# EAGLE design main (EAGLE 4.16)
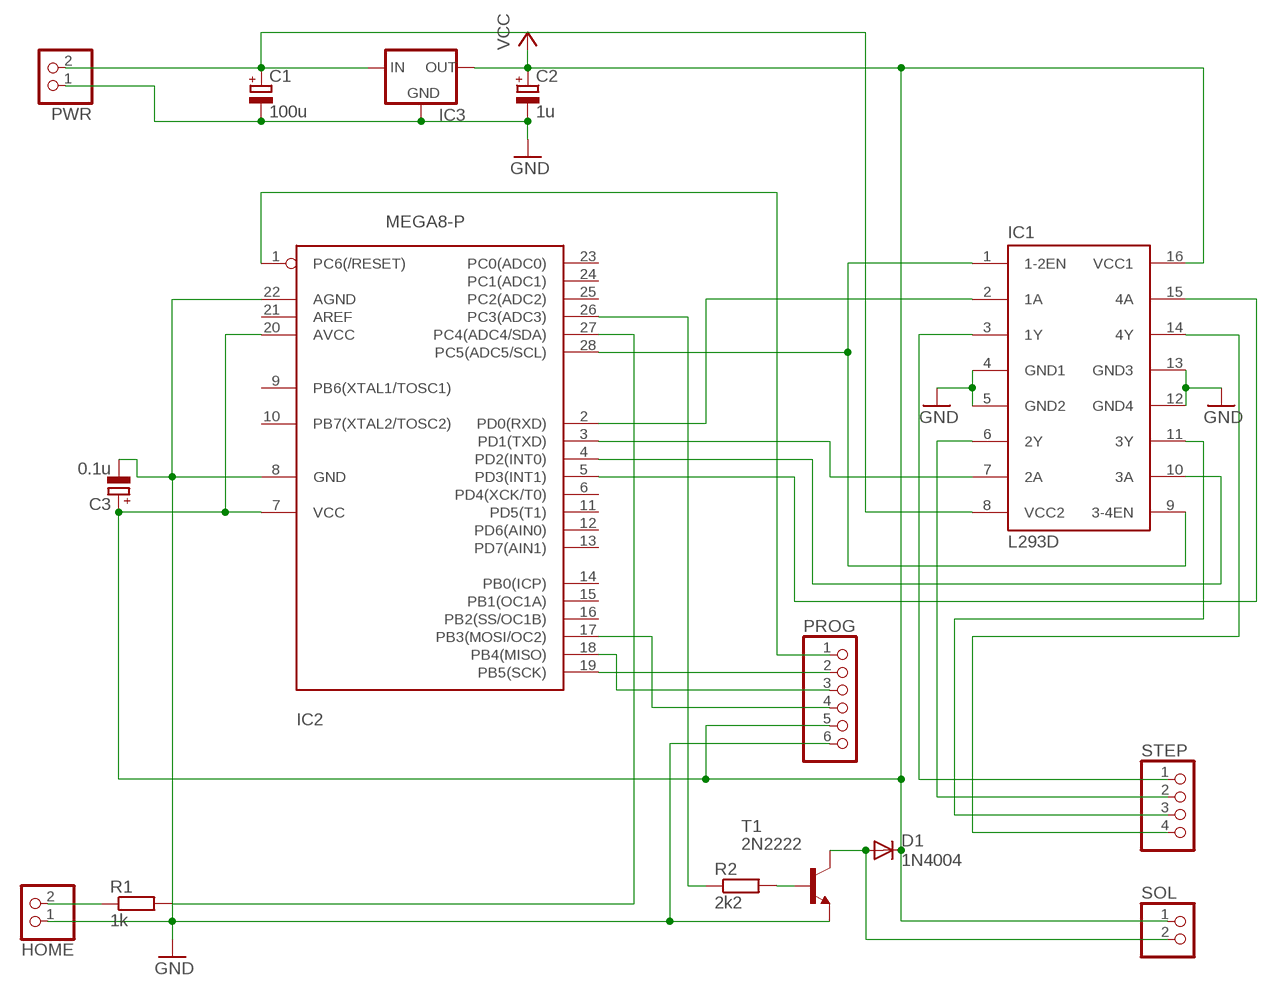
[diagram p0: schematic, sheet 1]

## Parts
C1  100u  CPOL-EUE2.5-7  [E2,5-7]
C2  1u  CPOL-EUE2.5-7  [E2,5-7]
C3  0.1u  CPOL-EUE2.5-7  [E2,5-7]
D1  1N4004  [DO41-10]
HOME  PINHD-1X2  [1X02]
IC1  L293D  [DIL16]
IC2  MEGA8-P  [DIL28-3]
IC3  78XXS  [78XXS]
PROG  PINHD-1X6  [1X06]
PWR  PINHD-1X2  [1X02]
R1  1k  R-EU_0207/2V  [0207/2V]
R2  2k2  R-EU_0207/2V  [0207/2V]
SOL  PINHD-1X2  [1X02]
STEP  PINHD-1X4  [1X04]
T1  2N2222  [TO18]

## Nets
GND: C1.- C2.- C3.- HOME.1 IC1.4(GND1) IC1.5(GND2) IC1.12(GND4) IC1.13(GND3) IC2.8(GND) IC2.22(AGND) IC3.GND PROG.6 PWR.1 T1.1(E)
N$1: C1.+ IC1.8(VCC2) IC3.IN PWR.2
N$2: IC1.3(1Y) STEP.1
N$3: IC1.6(2Y) STEP.2
N$4: IC1.1(1-2EN) IC1.9(3-4EN) IC2.28(PC5(ADC5/SCL))
N$5: IC1.2(1A) IC2.2(PD0(RXD))
N$6: IC1.7(2A) IC2.3(PD1(TXD))
N$7: IC1.10(3A) IC2.4(PD2(INT0))
N$8: IC1.15(4A) IC2.5(PD3(INT1))
N$9: IC1.11(3Y) STEP.3
N$10: IC1.14(4Y) STEP.4
N$11: HOME.2 R1.1
N$12: IC2.27(PC4(ADC4/SDA)) R1.2
N$13: IC2.26(PC3(ADC3)) R2.1
N$14: R2.2 T1.2(B)
N$15: D1.A SOL.2 T1.3(C)
N$16: IC2.1(PC6(/RESET)) PROG.1
N$17: IC2.19(PB5(SCK)) PROG.2
N$18: IC2.18(PB4(MISO)) PROG.3
N$19: IC2.17(PB3(MOSI/OC2)) PROG.4
VCC: C2.+ C3.+ D1.C IC1.16(VCC1) IC2.7(VCC) IC2.20(AVCC) IC3.OUT PROG.5 SOL.1
Unconnected: IC2.6(PD4(XCK/T0)) IC2.9(PB6(XTAL1/TOSC1)) IC2.10(PB7(XTAL2/TOSC2)) IC2.11(PD5(T1)) IC2.12(PD6(AIN0)) IC2.13(PD7(AIN1)) IC2.14(PB0(ICP)) IC2.15(PB1(OC1A)) IC2.16(PB2(SS/OC1B)) IC2.21(AREF) IC2.23(PC0(ADC0)) IC2.24(PC1(ADC1)) IC2.25(PC2(ADC2))

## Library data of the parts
C1-C3 = rcl:CPOL-EU: POLARIZED CAPACITOR, European symbol
D1 = diode:1N4004: DIODE
HOME PWR SOL = pinhead:PINHD-1X2: PIN HEADER
IC1 = st-microelectronics:L293D: PUSH-PULL 4 CHANNEL DRIVER
IC2 = atmel:MEGA8-P: MICROCONTROLLER 8 Kbytes FLASH 1 kbytes SRAM 512 bytes EEPROM USART 4-channel 10 bit ADC 2-channel 8 bit ADC Source: avr.lbr
IC3 = v-reg:78XXS: VOLTAGE REGULATOR
PROG = pinhead:PINHD-1X6: PIN HEADER
R1 R2 = rcl:R-EU_: RESISTOR, European symbol
STEP = pinhead:PINHD-1X4: PIN HEADER
T1 = transistor:2N2222: NPN TRANSISTOR

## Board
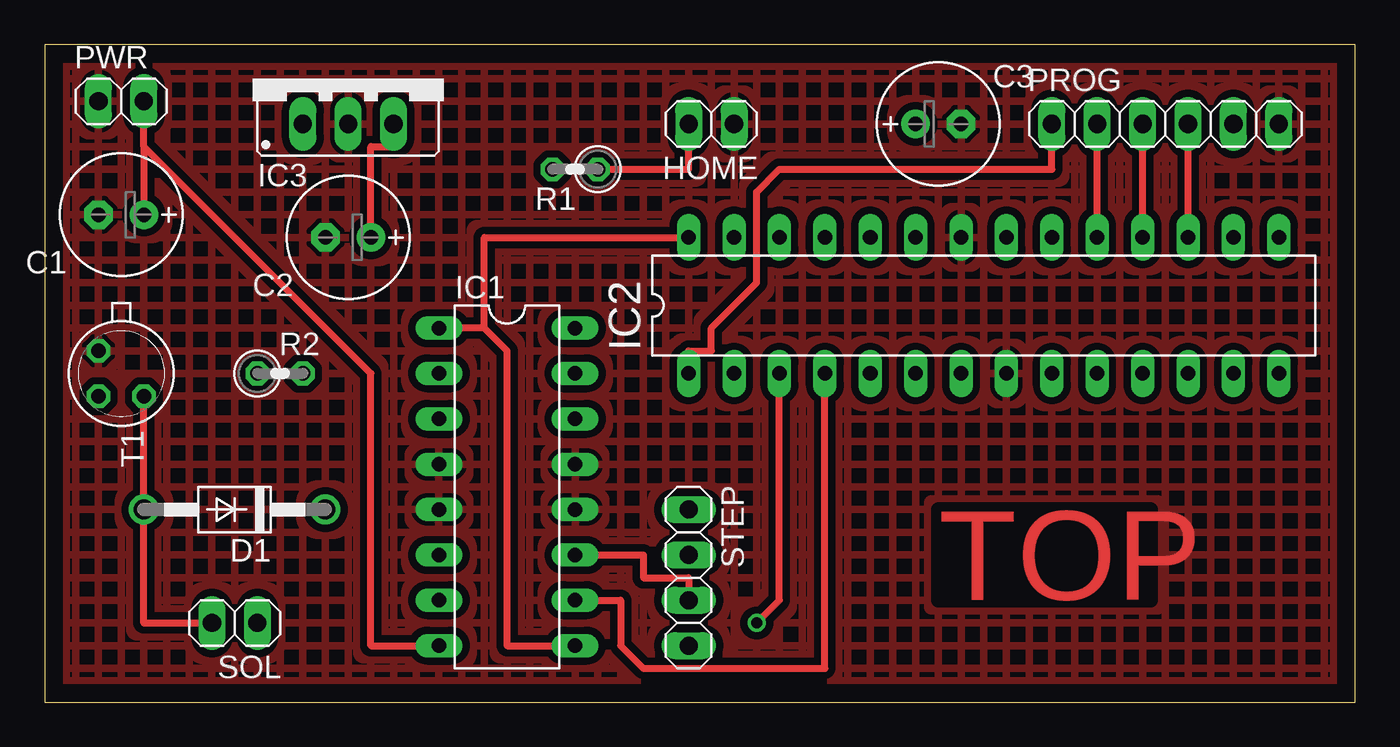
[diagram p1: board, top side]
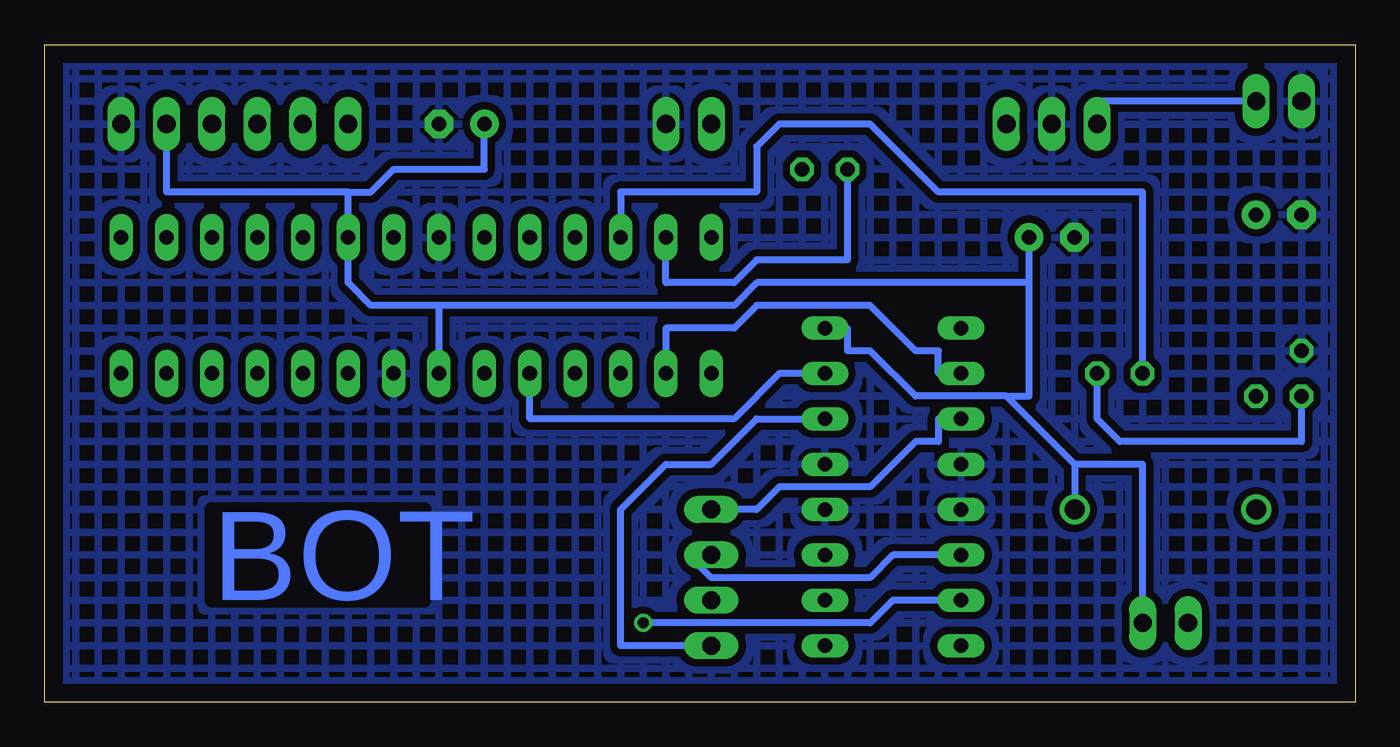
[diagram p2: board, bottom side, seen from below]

Size 73.33 x 36.82 mm. Coordinates in mm from the lower left corner, seen from the top.
Outline: 0,0 73.33,0 73.33,36.82 0,36.82 0,0
Copper layers (1*16): Top 0.035mm / dielectric 1.5mm / Bottom 0.035mm
Design rules "default": minimum track width 15mil, minimum drill 24mil, track to track 8mil, track to pad 8mil, pad to pad 8mil, via to via 8mil, smd to smd 8mil, copper to edge 40mil, drill to drill 8mil, minimum pad ring 10mil, minimum via ring 8mil, stop-mask expansion 4mil, vias tented up to drill 0mil, thermal gap 10mil

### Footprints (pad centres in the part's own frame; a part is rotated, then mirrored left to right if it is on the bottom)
E2,5-7 = drill 0.813 pad 1.6 round: + -1.27,0 | drill 0.813 pad 1.6 octagon: - 1.27,0
DO41-10 = drill 1.118 round: A 5.08,0; C -5.08,0
1X02 = drill 1.016 long: 1 -1.27,0; 2 1.27,0
DIL16 = drill 0.813 long: 1 -8.89,-3.81; 2 -6.35,-3.81; 3 -3.81,-3.81; 4 -1.27,-3.81; 5 1.27,-3.81; 6 3.81,-3.81; 7 6.35,-3.81; 8 8.89,-3.81; 9 8.89,3.81; 10 6.35,3.81; 11 3.81,3.81; 12 1.27,3.81; 13 -1.27,3.81; 14 -3.81,3.81; 15 -6.35,3.81; 16 -8.89,3.81
DIL28-3 = drill 0.813 long: 1 -16.51,-3.81; 2 -13.97,-3.81; 3 -11.43,-3.81; 4 -8.89,-3.81; 5 -6.35,-3.81; 6 -3.81,-3.81; 7 -1.27,-3.81; 8 1.27,-3.81; 9 3.81,-3.81; 10 6.35,-3.81; 11 8.89,-3.81; 12 11.43,-3.81; 13 13.97,-3.81; 14 16.51,-3.81; 15 16.51,3.81; 16 13.97,3.81; 17 11.43,3.81; 18 8.89,3.81; 19 6.35,3.81; 20 3.81,3.81; 21 1.27,3.81; 22 -1.27,3.81; 23 -3.81,3.81; 24 -6.35,3.81; 25 -8.89,3.81; 26 -11.43,3.81; 27 -13.97,3.81; 28 -16.51,3.81
78XXS = drill 1.016 long: GND 0,-2.54; IN -2.54,-2.54; OUT 2.54,-2.54
1X06 = drill 1.016 long: 1 -6.35,0; 2 -3.81,0; 3 -1.27,0; 4 1.27,0; 5 3.81,0; 6 6.35,0
0207/2V = drill 0.813 octagon: 1 -1.27,0; 2 1.27,0
1X04 = drill 1.016 long: 1 -3.81,0; 2 -1.27,0; 3 1.27,0; 4 3.81,0
TO18 = drill 0.813 octagon: 1 -1.27,-1.27; 2 1.27,-1.27; 3 1.27,1.27

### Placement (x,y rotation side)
C1  4.28,27.3 180 top
C2  16.98,26.03 180 top
C3  50,32.38 0 top
D1  10.63,10.79 180 top
HOME  37.3,32.38 180 top
IC1  25.87,12.06 270 top
IC2  52.54,22.22 0 top
IC3  16.98,34.92 0 top
PROG  62.7,32.38 0 top
PWR  4.28,33.65 0 top
R1  29.68,29.84 180 top
R2  13.17,18.41 0 top
SOL  10.63,4.44 180 top
STEP  36.03,6.98 270 top
T1  4.28,18.41 270 top

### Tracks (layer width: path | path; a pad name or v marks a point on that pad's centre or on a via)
GND
  pour Bottom (isolate 0.406, hatched): -0.8,38.73 74.13,38.73 74.13,-3.18 -0.8,-3.18
  pour Top (isolate 0.406, hatched): -0.8,38.73 74.13,38.73 74.13,-3.18 -0.8,-3.18
N$1
  Top 0.381: 5.55,31.11 18.25,18.41 18.25,3.17 IC1.8 | 5.55,31.11 PWR.2 | 5.55,31.11 C1.+
  Bottom 0.381: PWR.2 14.44,33.65 IC3.IN
N$2
  Bottom 0.381: IC1.3 23.33,15.87 23.33,14.6 24.6,14.6 27.14,12.06 32.22,12.06 33.49,10.79 STEP.1
N$3
  Bottom 0.381: IC1.6 25.87,8.25 27.14,6.98 36.03,6.98 37.3,8.25 STEP.2
N$4
  Top 0.381: 24.6,20.95 25.87,19.68 25.87,3.17 IC1.9 | 24.6,20.95 IC1.1 | IC2.28 24.6,26.03 24.6,20.95
N$5
  Bottom 0.381: IC1.2 23.33,18.41 23.33,19.68 24.6,19.68 27.14,22.22 33.49,22.22 34.76,20.95 38.57,20.95 IC2.2
N$6  (via drill 0.61)
  Top 0.381: v39.84,4.44 41.11,5.71 IC2.3
  Bottom 0.381: v39.84,4.44 27.14,4.44 25.87,5.71 IC1.7
N$7
  Top 0.381: IC1.10 32.22,5.71 32.22,3.17 33.49,1.9 43.65,1.9 IC2.4
N$8
  Bottom 0.381: IC1.15 32.22,18.41 34.76,15.87 46.19,15.87 IC2.5
N$9
  Top 0.381: STEP.3 36.03,6.98 33.49,6.98 33.49,8.25 IC1.11
N$10
  Bottom 0.381: IC1.14 33.49,15.87 36.03,13.33 38.57,13.33 41.11,10.79 41.11,3.17 STEP.4
N$11
  Top 0.381: R1.1 36.03,29.84 HOME.2
N$12
  Bottom 0.381: R1.2 28.41,24.76 33.49,24.76 34.76,23.49 38.57,23.49 IC2.27
N$13
  Bottom 0.381: R2.1 11.9,28.57 23.33,28.57 27.14,32.38 32.22,32.38 33.49,31.11 33.49,28.57 41.11,28.57 IC2.26
N$14
  Bottom 0.381: T1.2 3.01,14.6 13.17,14.6 14.44,15.87 R2.2
N$15
  Top 0.381: T1.3 D1.A 5.55,4.44 SOL.2
N$16
  Top 0.381: IC2.1 36.03,19.68 37.3,19.68 37.3,20.95 39.84,23.49 39.84,28.57 41.11,29.84 56.35,29.84 PROG.1
N$17
  Top 0.381: IC2.19 PROG.2
N$18
  Top 0.381: IC2.18 PROG.3
N$19
  Top 0.381: IC2.17 PROG.4
VCC
  Top 0.381: C2.+ 18.25,31.11 19.52,31.11 IC3.OUT
  Bottom 0.381: 51.27,22.22 55.08,22.22 56.35,23.49 IC2.20 56.35,28.57 | 51.27,22.22 IC2.7 | 56.35,28.57 66.51,28.57 PROG.5 | C3.+ 48.73,29.84 53.81,29.84 55.08,28.57 56.35,28.57 | 19.52,17.14 24.6,17.14 27.14,19.68 28.41,19.68 28.41,20.95 IC1.16 | 15.71,13.33 19.52,17.14 | 15.71,13.33 D1.C | 15.71,13.33 11.9,13.33 SOL.1 | 18.25,23.49 18.25,17.14 19.52,17.14 | 18.25,23.49 C2.+ | 51.27,22.22 34.76,22.22 33.49,23.49 18.25,23.49

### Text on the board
Top: TOP
Bottom: BOT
